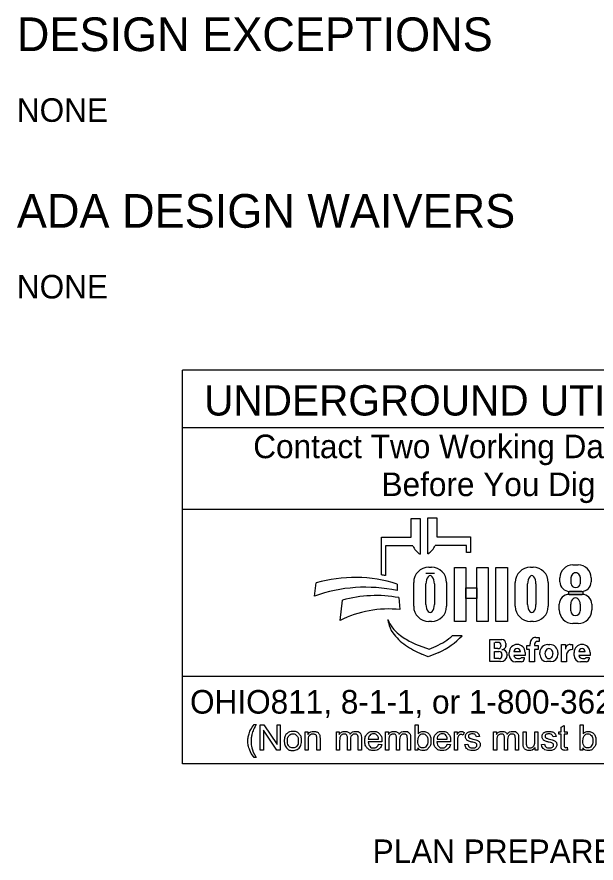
# Model space of a CAD drawing. Extents: x -13.9 to 69.1, y -25.2 to 26.1.
# Drawn here: x 1.73 to 5.16, y -24.13 to -19.11 of the extents above; entities that cross this region are included whole.
import ezdxf

# ---------------------------------------------------------------- set-up
doc = ezdxf.new("R2010")
doc.units = 0
doc.layers.add('SH_Data', color=7, linetype='Continuous')
doc.layers.add('SH_Text', color=7, linetype='Continuous')

msp = doc.modelspace()

# ---------------------------------------------------------------- linework, layer by layer
at = {"layer": 'SH_Data'}
for p, q in [((2.7083, -23.5439), (2.7083, -21.2064)), ((6.9583, -21.2064), (2.7083, -21.2064)), ((2.7083, -21.5479), (6.9583, -21.5479)), ((2.7083, -22.0313), (6.9583, -22.0313)), ((6.9583, -23.026), (2.7083, -23.026)), ((6.9583, -23.5439), (2.7083, -23.5439))]:
    msp.add_line(p, q, dxfattribs=at)
at = {"layer": 'SH_Text'}
for p, q in [((4.0643, -22.1983), (4.0643, -22.0869)), ((4.0643, -22.0869), (4.118, -22.0869)), ((4.118, -22.0869), (4.118, -22.2989)), ((4.1636, -22.2966), (4.1636, -22.0845)), ((4.1636, -22.0845), (4.2173, -22.0845)), ((4.2173, -22.0845), (4.2173, -22.196)), ((3.8884, -22.4222), (3.8884, -22.1983)), ((3.8884, -22.1983), (4.0643, -22.1983)), ((4.2173, -22.196), (4.4165, -22.196)), ((4.4165, -22.196), (4.4165, -22.2898)), ((3.9136, -22.2498), (3.9136, -22.4266)), ((4.0747, -22.2498), (3.9136, -22.2498)), ((4.3932, -22.2475), (4.2069, -22.2475)), ((4.3932, -22.2898), (4.3932, -22.2475)), ((4.4165, -22.2898), (4.3932, -22.2898)), ((4.1693, -22.3775), (4.1859, -22.3775)), ((4.7724, -22.3775), (4.7889, -22.3775)), ((5.0239, -22.3635), (5.0566, -22.3635)), ((4.2026, -22.4145), (4.1528, -22.4145)), ((4.9476, -22.4641), (4.9476, -22.4398)), ((5.0137, -22.4755), (5.0137, -22.4362)), ((5.0679, -22.4362), (5.0679, -22.4755)), ((5.1329, -22.4398), (5.1329, -22.4641)), ((3.491, -22.5485), (3.5004, -22.4704)), ((3.9817, -22.4769), (3.9817, -22.5157)), ((4.0798, -22.609), (4.0798, -22.467)), ((4.1528, -22.5976), (4.1528, -22.4753)), ((4.2026, -22.4753), (4.2026, -22.5976)), ((4.2753, -22.467), (4.2753, -22.609)), ((4.6829, -22.609), (4.6829, -22.467)), ((4.7558, -22.5976), (4.7558, -22.4753)), ((4.8056, -22.4753), (4.8056, -22.5976)), ((4.8784, -22.467), (4.8784, -22.609)), ((3.9916, -22.5575), (3.9979, -22.6285)), ((5.0018, -22.5384), (5.0791, -22.5384)), ((5.0769, -22.5201), (5.0036, -22.5201)), ((3.6428, -22.6931), (3.6575, -22.5729)), ((4.9439, -22.6304), (4.9439, -22.5963)), ((5.0114, -22.6363), (5.0114, -22.5954)), ((5.0682, -22.5954), (5.0682, -22.6363)), ((5.137, -22.5963), (5.137, -22.6304)), ((3.9305, -22.706), (3.9275, -22.688)), ((4.1859, -22.6985), (4.1693, -22.6985)), ((4.7889, -22.6985), (4.7724, -22.6985)), ((5.056, -22.7113), (5.0248, -22.7113)), ((4.3108, -22.7818), (4.3682, -22.7818)), ((4.5321, -22.9376), (4.5321, -22.8069)), ((4.5321, -22.8069), (4.6033, -22.8069)), ((4.8047, -22.7941), (4.8241, -22.7941)), ((4.8241, -22.7941), (4.8241, -22.8171)), ((4.1124, -22.8422), (4.1718, -22.8627)), ((4.1718, -22.8627), (4.2128, -22.8449)), ((4.5601, -22.8604), (4.5601, -22.8234)), ((4.5795, -22.8604), (4.5601, -22.8604)), ((4.5853, -22.8234), (4.564, -22.8234)), ((4.627, -22.8306), (4.627, -22.8385)), ((4.7521, -22.8654), (4.7521, -22.8425)), ((4.7521, -22.8425), (4.7714, -22.8425)), ((4.7714, -22.8425), (4.7714, -22.832)), ((4.7975, -22.834), (4.7975, -22.8425)), ((4.7975, -22.8425), (4.8191, -22.8425)), ((4.8241, -22.8175), (4.814, -22.8175)), ((4.8191, -22.8425), (4.8191, -22.8654)), ((4.8759, -22.8359), (4.888, -22.8359)), ((4.9561, -22.9388), (4.9561, -22.8361)), ((4.9561, -22.8361), (4.9807, -22.8361)), ((4.9807, -22.8361), (4.9807, -22.863)), ((5.0079, -22.8361), (5.0218, -22.8361)), ((5.0218, -22.8361), (5.0218, -22.8658)), ((4.1658, -22.9097), (4.1284, -22.8933)), ((4.2291, -22.8823), (4.1658, -22.9097)), ((4.5601, -22.9198), (4.5601, -22.8769)), ((4.5601, -22.8769), (4.5856, -22.8769)), ((4.6037, -22.895), (4.6037, -22.9014)), ((4.6351, -22.8979), (4.6351, -22.8983)), ((4.6466, -22.9008), (4.6466, -22.8824)), ((4.7132, -22.8784), (4.6747, -22.8784)), ((4.7412, -22.9001), (4.6748, -22.9001)), ((4.7412, -22.8824), (4.7412, -22.9001)), ((4.767, -22.8654), (4.7521, -22.8654)), ((4.767, -22.9388), (4.767, -22.8654)), ((4.8191, -22.8654), (4.7975, -22.8654)), ((4.7975, -22.8654), (4.7975, -22.9388)), ((4.8281, -22.8945), (4.8281, -22.8837)), ((4.9358, -22.8837), (4.9358, -22.8945)), ((4.9867, -22.9007), (4.9867, -22.9388)), ((5.0316, -22.9008), (5.0316, -22.8824)), ((5.0981, -22.8784), (5.0596, -22.8784)), ((5.1261, -22.9001), (5.0597, -22.9001)), ((5.1261, -22.8824), (5.1261, -22.9001)), ((4.5958, -22.9376), (4.5321, -22.9376)), ((4.5853, -22.9198), (4.5601, -22.9198)), ((4.72, -22.9388), (4.6846, -22.9388)), ((4.6957, -22.9193), (4.7098, -22.9193)), ((4.7184, -22.9138), (4.7352, -22.9138)), ((4.7352, -22.9138), (4.7352, -22.9236)), ((4.7975, -22.9388), (4.767, -22.9388)), ((4.8931, -22.9373), (4.8709, -22.9373)), ((4.9867, -22.9388), (4.9561, -22.9388)), ((5.1049, -22.9388), (5.0695, -22.9388)), ((5.0806, -22.9193), (5.0947, -22.9193)), ((5.1033, -22.9138), (5.1202, -22.9138)), ((5.1202, -22.9138), (5.1202, -22.9236))]:
    msp.add_line(p, q, dxfattribs=at)
for points in [[(4.3217, -22.3786), (4.3897, -22.3786), (4.3897, -22.6986), (4.3217, -22.6986)], [(4.4539, -22.3786), (4.5219, -22.3786), (4.5219, -22.6986), (4.4539, -22.6986)], [(4.5672, -22.3786), (4.636, -22.3786), (4.636, -22.6986), (4.5672, -22.6986)], [(4.3897, -22.4985), (4.4539, -22.4985), (4.4539, -22.5625), (4.3897, -22.5625)], [(5.0014, -22.5201), (5.0831, -22.5201), (5.0831, -22.5386), (5.0014, -22.5386)]]:
    msp.add_lwpolyline(points, close=True, dxfattribs=at)
for points in [[(3.1329, -23.3101), (3.1461, -23.3101)], [(3.1697, -23.4627), (3.1697, -23.3126), (3.19, -23.3126), (3.269, -23.4305), (3.269, -23.3126), (3.288, -23.3126), (3.288, -23.4627), (3.2677, -23.4627), (3.1886, -23.3448), (3.1886, -23.4627), (3.1697, -23.4627)], [(4.1051, -23.4627), (4.0881, -23.4627), (4.0881, -23.3126), (4.1065, -23.3126), (4.1065, -23.3661)], [(5.0842, -23.4627), (5.0671, -23.4627), (5.0671, -23.3126), (5.0856, -23.3126), (5.0856, -23.3661)], [(3.4356, -23.4627), (3.4356, -23.3539), (3.4522, -23.3539), (3.4522, -23.3694)], [(3.622, -23.4627), (3.622, -23.3539), (3.6385, -23.3539), (3.6385, -23.3692)], [(3.9134, -23.4627), (3.9134, -23.3539), (3.9299, -23.3539), (3.9299, -23.3692)], [(4.3212, -23.4627), (4.3212, -23.3539), (4.3378, -23.3539), (4.3378, -23.3704)], [(4.3802, -23.3574), (4.3738, -23.3744)], [(4.5544, -23.4627), (4.5544, -23.3539), (4.5709, -23.3539), (4.5709, -23.3692)], [(4.7287, -23.4213), (4.7287, -23.3539), (4.7471, -23.3539), (4.7471, -23.4142)], [(4.7984, -23.4122), (4.7984, -23.3539), (4.8168, -23.3539), (4.8168, -23.4627), (4.8004, -23.4627)], [(4.9541, -23.4309), (4.9541, -23.3682), (4.9404, -23.3682), (4.9404, -23.3539), (4.9541, -23.3539), (4.9541, -23.3269), (4.9725, -23.3159), (4.9725, -23.3539), (4.9909, -23.3539), (4.9909, -23.3682), (4.9725, -23.3682), (4.9725, -23.432)], [(3.454, -23.4033), (3.454, -23.4627), (3.4356, -23.4627)], [(3.524, -23.3958), (3.524, -23.4627), (3.5055, -23.4627), (3.5055, -23.3966)], [(3.6405, -23.4063), (3.6405, -23.4627), (3.622, -23.4627)], [(3.7051, -23.3996), (3.7051, -23.4627), (3.6867, -23.4627), (3.6867, -23.3921)], [(3.7695, -23.3881), (3.7695, -23.4627), (3.7511, -23.4627), (3.7511, -23.3942)], [(3.8908, -23.4131), (3.8096, -23.4131)], [(3.8106, -23.3979), (3.8714, -23.3979)], [(3.9318, -23.4063), (3.9318, -23.4627), (3.9134, -23.4627)], [(3.9965, -23.3996), (3.9965, -23.4627), (3.9781, -23.4627), (3.9781, -23.3921)], [(4.0609, -23.3881), (4.0609, -23.4627), (4.0425, -23.4627), (4.0425, -23.3942)], [(4.2988, -23.4131), (4.2176, -23.4131)], [(4.2186, -23.3979), (4.2794, -23.3979)], [(4.3396, -23.4057), (4.3396, -23.4627), (4.3212, -23.4627)], [(4.4702, -23.382), (4.4521, -23.3844)], [(4.5728, -23.4063), (4.5728, -23.4627), (4.5544, -23.4627)], [(4.6375, -23.3996), (4.6375, -23.4627), (4.6191, -23.4627), (4.6191, -23.3921)], [(4.7019, -23.3881), (4.7019, -23.4627), (4.6835, -23.4627), (4.6835, -23.3942)], [(4.9248, -23.382), (4.9067, -23.3844)], [(3.8712, -23.4276), (3.8903, -23.43)], [(4.1051, -23.4491), (4.1051, -23.4627)], [(4.2792, -23.4276), (4.2983, -23.43)], [(4.3838, -23.4302), (4.402, -23.4274)], [(4.8004, -23.4627), (4.8004, -23.4467)], [(4.8384, -23.4302), (4.8565, -23.4274)], [(4.9909, -23.4463), (4.9935, -23.4626)], [(5.0842, -23.4491), (5.0842, -23.4627)], [(3.1461, -23.5069), (3.1329, -23.5069)]]:
    msp.add_lwpolyline(points, dxfattribs=at)
for centre, radius, start, end in [((4.1661, -22.213), 0.0985, 201.9296, 240.7469), ((4.1155, -22.2107), 0.0985, 299.2531, 338.0704), ((4.1693, -22.467), 0.0895, 90, 180), ((4.1859, -22.467), 0.0895, 0, 90), ((4.7724, -22.467), 0.0895, 90, 180), ((4.7889, -22.467), 0.0895, 0, 90), ((5.0239, -22.4398), 0.0763, 90, 180), ((5.0566, -22.4398), 0.0763, 0, 90), ((3.7305, -23.2565), 0.8191, 72.1402, 106.3144), ((3.7602, -23.2312), 0.8191, 79.2074, 81.0007), ((3.7935, -23.3876), 0.8919, 77.8238, 109.8274), ((5.0036, -22.4641), 0.056, 180, 270), ((5.0769, -22.4641), 0.056, 270, 0), ((3.8574, -23.2773), 0.7322, 79.44, 105.8467), ((5.0018, -22.5963), 0.0579, 90, 180), ((5.0791, -22.5963), 0.0579, 0, 90), ((4.1693, -22.609), 0.0895, 180, 270), ((4.1859, -22.609), 0.0895, 270, 0), ((4.7724, -22.609), 0.0895, 180, 270), ((4.7889, -22.609), 0.0895, 270, 0), ((3.9295, -23.2605), 0.6357, 83.8248, 116.8021), ((5.0248, -22.6304), 0.081, 180, 270), ((5.056, -22.6304), 0.081, 270, 0), ((4.1148, -22.6159), 0.2008, 201.0457, 232.5314), ((4.0718, -22.6819), 0.1433, 189.6817, 216.0884), ((4.2055, -22.5844), 0.3088, 216.0884, 235.7167), ((4.3074, -22.3647), 0.5173, 232.5314, 241.794), ((4.0694, -22.5144), 0.3602, 293.4582, 312.0712), ((4.0694, -22.5144), 0.401, 293.4582, 317.8286), ((4.6033, -22.8306), 0.0238, 0, 90), ((4.8047, -22.8276), 0.0335, 90, 187.5187), ((4.372, -22.3402), 0.6044, 235.7167, 246.2325), ((4.2222, -22.5235), 0.3371, 241.794, 250.9821), ((4.5795, -22.8416), 0.0187, 270, 2.0582), ((4.5813, -22.8403), 0.0169, 357.8325, 90), ((4.6029, -22.8414), 0.0243, 270, 6.6529), ((4.6135, -22.8428), 0.0175, 347.4023, 0), ((4.6939, -22.8824), 0.0473, 0, 180), ((4.694, -22.8794), 0.0193, 2.9632, 177.0368), ((4.814, -22.834), 0.0165, 90, 180), ((4.8759, -22.8837), 0.0478, 90, 180), ((4.888, -22.8837), 0.0478, 0, 90), ((5.0076, -22.863), 0.0269, 89.2449, 180), ((5.0788, -22.8824), 0.0473, 0, 180), ((5.0789, -22.8794), 0.0193, 2.9632, 177.0368), ((4.5853, -22.9014), 0.0184, 270, 0), ((4.5856, -22.895), 0.0181, 0, 90), ((4.5958, -22.8983), 0.0393, 270, 0), ((4.603, -22.8978), 0.0321, 4.0748, 90), ((4.6021, -22.8979), 0.033, 0, 11.7502), ((4.6846, -22.9008), 0.038, 180, 270), ((4.6957, -22.8983), 0.021, 184.827, 270), ((4.8709, -22.8945), 0.0428, 180, 270), ((4.8931, -22.8945), 0.0428, 270, 0), ((5.0216, -22.9007), 0.0349, 89.6033, 180), ((5.0695, -22.9008), 0.038, 180, 270), ((5.0806, -22.8983), 0.021, 184.827, 270), ((4.7098, -22.9099), 0.00938, 270, 335.9979), ((4.72, -22.9236), 0.0152, 270, 0), ((5.0947, -22.9099), 0.00938, 270, 335.9979), ((5.1049, -22.9236), 0.0152, 270, 0)]:
    msp.add_arc(centre, radius, start, end, dxfattribs=at)
for centre, major_axis, ratio, start_param, end_param in [((4.1777, -22.4753), (0, 0.0484), 0.514403, 4.712389, 7.853982), ((4.7807, -22.4753), (0, 0.0484), 0.514403, 4.712389, 7.853982), ((5.0408, -22.4362), (0.0271, 0), 0.969373, 0, 3.141593), ((5.0408, -22.4755), (0.0271, 0), 0.818453, 3.141593, 6.283185), ((4.1777, -22.5976), (0, 0.0484), 0.514403, 1.570796, 4.712389), ((4.7807, -22.5976), (0, 0.0484), 0.514403, 1.570796, 4.712389), ((5.0398, -22.5954), (0, 0.0358), 0.794529, 4.712389, 7.853982), ((5.0398, -22.6363), (0.0284, 0), 0.959837, 3.141593, 6.283185), ((4.8824, -22.8891), (0, 0.029), 0.832186, 4.712389, 7.853982), ((4.8824, -22.8891), (0, 0.0302), 0.797287, 1.570796, 4.712389)]:
    msp.add_ellipse(centre, major_axis=major_axis, ratio=ratio, start_param=start_param, end_param=end_param, dxfattribs=at)
for points in [[(3.1329, -23.5069), (3.1176, -23.4876), (3.1071, -23.4618), (3.0965, -23.436), (3.0965, -23.4084), (3.0965, -23.384), (3.1044, -23.3617), (3.1136, -23.3358), (3.1329, -23.3101)], [(3.1461, -23.3101), (3.1337, -23.3314), (3.1297, -23.3405), (3.1235, -23.3546), (3.1199, -23.37), (3.1155, -23.3891), (3.1155, -23.4085), (3.1155, -23.4577), (3.1461, -23.5069)], [(3.3121, -23.4083), (3.3121, -23.3781), (3.3289, -23.3636), (3.3429, -23.3515), (3.3631, -23.3515), (3.3855, -23.3515), (3.3998, -23.3662), (3.414, -23.3809), (3.414, -23.4068), (3.414, -23.4278), (3.4077, -23.4398), (3.4014, -23.4518), (3.3894, -23.4585), (3.3773, -23.4651), (3.3631, -23.4651), (3.3403, -23.4651), (3.3262, -23.4505), (3.3121, -23.4358), (3.3121, -23.4083)], [(3.4522, -23.3694), (3.4642, -23.3515), (3.4868, -23.3515), (3.4966, -23.3515), (3.5049, -23.355), (3.5131, -23.3585), (3.5172, -23.3643), (3.5213, -23.37), (3.5229, -23.3779), (3.524, -23.383), (3.524, -23.3958)], [(3.6385, -23.3692), (3.6436, -23.3612), (3.6521, -23.3564), (3.6606, -23.3515), (3.6715, -23.3515), (3.6836, -23.3515), (3.6913, -23.3565), (3.6991, -23.3615), (3.7022, -23.3706), (3.7152, -23.3515), (3.7359, -23.3515), (3.7521, -23.3515), (3.7608, -23.3604), (3.7695, -23.3694), (3.7695, -23.3881)], [(3.8903, -23.43), (3.8858, -23.4467), (3.8736, -23.4559), (3.8614, -23.4651), (3.8424, -23.4651), (3.8186, -23.4651), (3.8046, -23.4504), (3.7906, -23.4357), (3.7906, -23.4092), (3.7906, -23.3818), (3.8048, -23.3666), (3.8189, -23.3515), (3.8414, -23.3515), (3.8632, -23.3515), (3.877, -23.3663), (3.8909, -23.3812), (3.8909, -23.4081), (3.8909, -23.4098), (3.8908, -23.4131)], [(3.9299, -23.3692), (3.935, -23.3612), (3.9435, -23.3564), (3.952, -23.3515), (3.9629, -23.3515), (3.975, -23.3515), (3.9827, -23.3565), (3.9904, -23.3615), (3.9936, -23.3706), (4.0065, -23.3515), (4.0273, -23.3515), (4.0435, -23.3515), (4.0522, -23.3604), (4.0609, -23.3694), (4.0609, -23.3881)], [(4.1065, -23.3661), (4.1182, -23.3515), (4.1363, -23.3515), (4.1463, -23.3515), (4.1553, -23.3555), (4.1642, -23.3596), (4.17, -23.3669), (4.1758, -23.3742), (4.1791, -23.3846), (4.1824, -23.3949), (4.1824, -23.4067), (4.1824, -23.4346), (4.1685, -23.4499), (4.1547, -23.4651), (4.1353, -23.4651), (4.1161, -23.4651), (4.1051, -23.4491)], [(4.2983, -23.43), (4.2937, -23.4467), (4.2816, -23.4559), (4.2694, -23.4651), (4.2504, -23.4651), (4.2266, -23.4651), (4.2126, -23.4504), (4.1986, -23.4357), (4.1986, -23.4092), (4.1986, -23.3818), (4.2127, -23.3666), (4.2269, -23.3515), (4.2494, -23.3515), (4.2712, -23.3515), (4.285, -23.3663), (4.2989, -23.3812), (4.2989, -23.4081), (4.2989, -23.4098), (4.2988, -23.4131)], [(4.3378, -23.3704), (4.3441, -23.3588), (4.3495, -23.3552), (4.3549, -23.3515), (4.3613, -23.3515), (4.3706, -23.3515), (4.3802, -23.3574)], [(4.402, -23.4274), (4.4035, -23.4383), (4.4106, -23.4442), (4.4176, -23.45), (4.4302, -23.45), (4.443, -23.45), (4.4491, -23.4448), (4.4553, -23.4397), (4.4553, -23.4327), (4.4553, -23.4264), (4.4499, -23.4228), (4.4461, -23.4204), (4.431, -23.4166), (4.4107, -23.4115), (4.4028, -23.4077), (4.395, -23.404), (4.3909, -23.3974), (4.3869, -23.3908), (4.3869, -23.3828), (4.3869, -23.3755), (4.3902, -23.3693), (4.3935, -23.3632), (4.3993, -23.3591), (4.4036, -23.3559), (4.411, -23.3537), (4.4185, -23.3515), (4.427, -23.3515), (4.4398, -23.3515), (4.4495, -23.3552), (4.4592, -23.3589), (4.4638, -23.3652), (4.4684, -23.3715), (4.4702, -23.382)], [(4.5709, -23.3692), (4.576, -23.3612), (4.5845, -23.3564), (4.593, -23.3515), (4.6039, -23.3515), (4.616, -23.3515), (4.6237, -23.3565), (4.6314, -23.3615), (4.6346, -23.3706), (4.6475, -23.3515), (4.6683, -23.3515), (4.6845, -23.3515), (4.6932, -23.3604), (4.7019, -23.3694), (4.7019, -23.3881)], [(4.8565, -23.4274), (4.8581, -23.4383), (4.8651, -23.4442), (4.8722, -23.45), (4.8848, -23.45), (4.8975, -23.45), (4.9037, -23.4448), (4.9099, -23.4397), (4.9099, -23.4327), (4.9099, -23.4264), (4.9044, -23.4228), (4.9006, -23.4204), (4.8855, -23.4166), (4.8652, -23.4115), (4.8574, -23.4077), (4.8495, -23.404), (4.8455, -23.3974), (4.8414, -23.3908), (4.8414, -23.3828), (4.8414, -23.3755), (4.8448, -23.3693), (4.8481, -23.3632), (4.8539, -23.3591), (4.8582, -23.3559), (4.8656, -23.3537), (4.873, -23.3515), (4.8816, -23.3515), (4.8944, -23.3515), (4.9041, -23.3552), (4.9138, -23.3589), (4.9184, -23.3652), (4.923, -23.3715), (4.9248, -23.382)], [(5.0856, -23.3661), (5.0972, -23.3515), (5.1153, -23.3515), (5.1254, -23.3515), (5.1343, -23.3555), (5.1433, -23.3596), (5.1491, -23.3669), (5.1549, -23.3742), (5.1581, -23.3846), (5.1614, -23.3949), (5.1614, -23.4067), (5.1614, -23.4346), (5.1476, -23.4499), (5.1338, -23.4651), (5.1144, -23.4651), (5.0951, -23.4651), (5.0842, -23.4491)], [(3.3311, -23.4083), (3.3311, -23.4292), (3.3402, -23.4396), (3.3493, -23.45), (3.3631, -23.45), (3.3768, -23.45), (3.3859, -23.4396), (3.395, -23.4291), (3.395, -23.4077), (3.395, -23.3875), (3.3858, -23.3771), (3.3767, -23.3667), (3.3631, -23.3667), (3.3493, -23.3667), (3.3402, -23.3771), (3.3311, -23.3874), (3.3311, -23.4083)], [(3.5055, -23.3966), (3.5055, -23.3853), (3.5034, -23.3797), (3.5012, -23.3742), (3.4958, -23.3708), (3.4903, -23.3675), (3.4829, -23.3675), (3.4711, -23.3675), (3.4626, -23.375), (3.454, -23.3825), (3.454, -23.4033)], [(3.6867, -23.3921), (3.6867, -23.3798), (3.6822, -23.3736), (3.6777, -23.3675), (3.6674, -23.3675), (3.6596, -23.3675), (3.653, -23.3716), (3.6464, -23.3757), (3.6434, -23.3836), (3.6405, -23.3915), (3.6405, -23.4063)], [(3.7511, -23.3942), (3.7511, -23.3832), (3.7493, -23.3783), (3.7475, -23.3734), (3.7428, -23.3705), (3.7381, -23.3675), (3.7318, -23.3675), (3.7203, -23.3675), (3.7127, -23.3751), (3.7051, -23.3828), (3.7051, -23.3996)], [(3.8096, -23.4131), (3.8106, -23.431), (3.8198, -23.4405), (3.8289, -23.45), (3.8425, -23.45), (3.8527, -23.45), (3.8598, -23.4447), (3.867, -23.4393), (3.8712, -23.4276)], [(3.8714, -23.3979), (3.8702, -23.3842), (3.8644, -23.3773), (3.8556, -23.3666), (3.8416, -23.3666), (3.8289, -23.3666), (3.8202, -23.3751), (3.8116, -23.3837), (3.8106, -23.3979)], [(3.9781, -23.3921), (3.9781, -23.3798), (3.9735, -23.3736), (3.969, -23.3675), (3.9588, -23.3675), (3.951, -23.3675), (3.9444, -23.3716), (3.9378, -23.3757), (3.9348, -23.3836), (3.9318, -23.3915), (3.9318, -23.4063)], [(4.0425, -23.3942), (4.0425, -23.3832), (4.0407, -23.3783), (4.0389, -23.3734), (4.0342, -23.3705), (4.0295, -23.3675), (4.0231, -23.3675), (4.0116, -23.3675), (4.0041, -23.3751), (3.9965, -23.3828), (3.9965, -23.3996)], [(4.1049, -23.4075), (4.1049, -23.4271), (4.1102, -23.4358), (4.1189, -23.45), (4.1337, -23.45), (4.1458, -23.45), (4.1546, -23.4395), (4.1634, -23.429), (4.1634, -23.4082), (4.1634, -23.3869), (4.1549, -23.3767), (4.1465, -23.3666), (4.1345, -23.3666), (4.1225, -23.3666), (4.1137, -23.3771), (4.1049, -23.3876), (4.1049, -23.4075)], [(4.2176, -23.4131), (4.2186, -23.431), (4.2278, -23.4405), (4.2369, -23.45), (4.2505, -23.45), (4.2607, -23.45), (4.2678, -23.4447), (4.275, -23.4393), (4.2792, -23.4276)], [(4.2794, -23.3979), (4.2782, -23.3842), (4.2724, -23.3773), (4.2636, -23.3666), (4.2496, -23.3666), (4.2369, -23.3666), (4.2282, -23.3751), (4.2196, -23.3837), (4.2186, -23.3979)], [(4.3738, -23.3744), (4.3671, -23.3705), (4.3603, -23.3705), (4.3543, -23.3705), (4.3495, -23.3741), (4.3447, -23.3778), (4.3427, -23.3842), (4.3396, -23.3941), (4.3396, -23.4057)], [(4.4521, -23.3844), (4.4509, -23.376), (4.445, -23.3713), (4.4391, -23.3666), (4.4283, -23.3666), (4.4156, -23.3666), (4.4102, -23.3708), (4.4047, -23.375), (4.4047, -23.3806), (4.4047, -23.3842), (4.407, -23.3871), (4.4092, -23.3901), (4.4141, -23.392), (4.4168, -23.3931), (4.4304, -23.3968), (4.45, -23.402), (4.4577, -23.4053), (4.4655, -23.4086), (4.4699, -23.415), (4.4743, -23.4213), (4.4743, -23.4307), (4.4743, -23.4399), (4.4689, -23.4481), (4.4635, -23.4562), (4.4534, -23.4607), (4.4432, -23.4651), (4.4304, -23.4651), (4.4091, -23.4651), (4.398, -23.4563), (4.3869, -23.4475), (4.3838, -23.4302)], [(4.6191, -23.3921), (4.6191, -23.3798), (4.6145, -23.3736), (4.61, -23.3675), (4.5998, -23.3675), (4.592, -23.3675), (4.5854, -23.3716), (4.5788, -23.3757), (4.5758, -23.3836), (4.5728, -23.3915), (4.5728, -23.4063)], [(4.6835, -23.3942), (4.6835, -23.3832), (4.6817, -23.3783), (4.6799, -23.3734), (4.6752, -23.3705), (4.6705, -23.3675), (4.6641, -23.3675), (4.6526, -23.3675), (4.6451, -23.3751), (4.6375, -23.3828), (4.6375, -23.3996)], [(4.7471, -23.4142), (4.7471, -23.4286), (4.7483, -23.4337), (4.75, -23.4409), (4.7556, -23.4451), (4.7613, -23.4492), (4.7696, -23.4492), (4.7778, -23.4492), (4.7851, -23.445), (4.7924, -23.4407), (4.7954, -23.4334), (4.7984, -23.4261), (4.7984, -23.4122)], [(4.9067, -23.3844), (4.9054, -23.376), (4.8995, -23.3713), (4.8937, -23.3666), (4.8829, -23.3666), (4.8702, -23.3666), (4.8647, -23.3708), (4.8593, -23.375), (4.8593, -23.3806), (4.8593, -23.3842), (4.8616, -23.3871), (4.8638, -23.3901), (4.8686, -23.392), (4.8714, -23.3931), (4.8849, -23.3968), (4.9045, -23.402), (4.9123, -23.4053), (4.92, -23.4086), (4.9245, -23.415), (4.9289, -23.4213), (4.9289, -23.4307), (4.9289, -23.4399), (4.9235, -23.4481), (4.9181, -23.4562), (4.9079, -23.4607), (4.8978, -23.4651), (4.8849, -23.4651), (4.8637, -23.4651), (4.8526, -23.4563), (4.8414, -23.4475), (4.8384, -23.4302)], [(5.0839, -23.4075), (5.0839, -23.4271), (5.0893, -23.4358), (5.098, -23.45), (5.1128, -23.45), (5.1248, -23.45), (5.1336, -23.4395), (5.1424, -23.429), (5.1424, -23.4082), (5.1424, -23.3869), (5.134, -23.3767), (5.1256, -23.3666), (5.1136, -23.3666), (5.1015, -23.3666), (5.0927, -23.3771), (5.0839, -23.3876), (5.0839, -23.4075)], [(4.8004, -23.4467), (4.7877, -23.4651), (4.7659, -23.4651), (4.7562, -23.4651), (4.7479, -23.4614), (4.7396, -23.4578), (4.7355, -23.4522), (4.7315, -23.4466), (4.7298, -23.4385), (4.7287, -23.4331), (4.7287, -23.4213)], [(4.9935, -23.4626), (4.9858, -23.4642), (4.9796, -23.4642), (4.9696, -23.4642), (4.9641, -23.461), (4.9586, -23.4578), (4.9563, -23.4527), (4.9541, -23.4475), (4.9541, -23.4309)], [(4.9725, -23.432), (4.9725, -23.4399), (4.9734, -23.4421), (4.9744, -23.4444), (4.9766, -23.4457), (4.9788, -23.447), (4.9829, -23.447), (4.9859, -23.447), (4.9909, -23.4463)]]:
    msp.add_open_spline(points, degree=3, dxfattribs=at)

# ---------------------------------------------------------------- texts
for s, height, p in [('DESIGN EXCEPTIONS', 0.2, (1.7252, -19.3123)), ('NONE', 0.14, (1.7252, -19.7323)), ('ADA DESIGN WAIVERS', 0.2, (1.7252, -20.361)), ('NONE', 0.14, (1.7252, -20.781)), ('UNDERGROUND UTILITIES', 0.18, (2.8364, -21.476)), ('Contact Two Working Days', 0.14, (3.1279, -21.7295)), ('Before You Dig', 0.14, (3.8891, -21.9545)), ('OHIO811, 8-1-1, or 1-800-362-2764', 0.14, (2.7528, -23.246)), ('PLAN PREPARED BY:', 0.14, (3.8361, -24.1336))]:
    msp.add_text(s, height=height, dxfattribs=at).set_placement(p)

doc.saveas('drawing.dxf')
